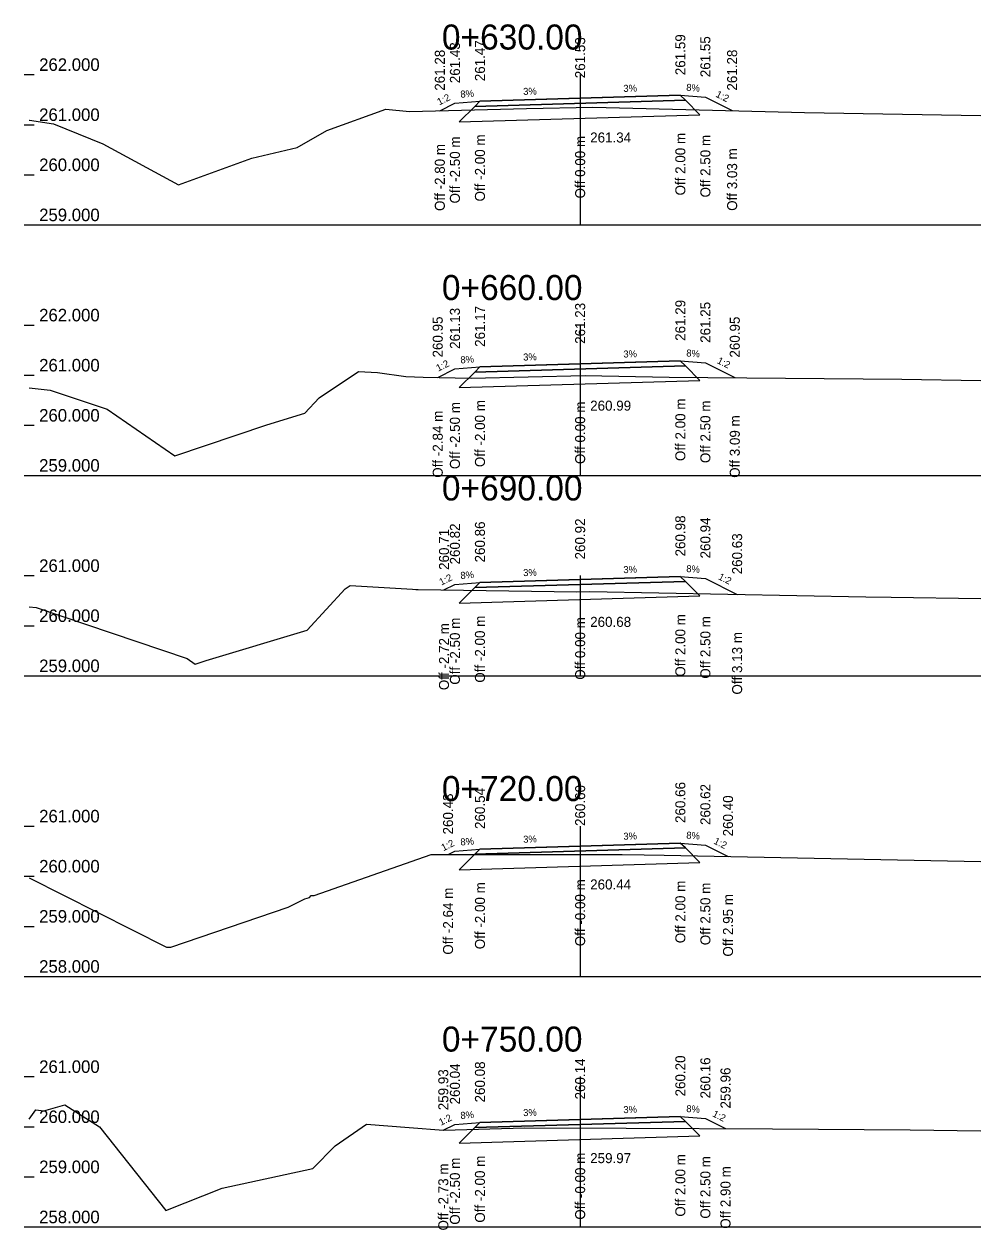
# Model space of a CAD drawing. Extents: x -550605 to -538780, y -1102367 to -1093705.
# Drawn here: x -541289.9 to -541270.8, y -1098198.61 to -1098174.55 of the extents above; entities that cross this region are included whole.
import ezdxf

# ---------------------------------------------------------------- set-up
doc = ezdxf.new("R2010")
doc.units = 0
for name, color, linetype in [('PŘ - offsety od osy', 7, 'Continuous'), ('PŘ - popis', 7, 'Continuous'), ('PŘ - příčné sklony', 7, 'Continuous'), ('PŘ - terén', 7, 'Continuous'), ('PŘ - vozovka', 7, 'Continuous'), ('PŘ - výšky offsetů', 7, 'Continuous')]:
    doc.layers.add(name, color=color, linetype=linetype)

msp = doc.modelspace()

# ---------------------------------------------------------------- linework, layer by layer
at = {"layer": 'PŘ - popis'}
for p, q in [((-541289.898, -1098175.553), (-541289.698, -1098175.553)), ((-541278.798, -1098175.553), (-541278.798, -1098178.553)), ((-541289.898, -1098176.553), (-541289.698, -1098176.553)), ((-541289.898, -1098177.553), (-541289.698, -1098177.553)), ((-541289.898, -1098178.553), (-541289.698, -1098178.553)), ((-541289.798, -1098178.553), (-541270.798, -1098178.553)), ((-541289.898, -1098180.553), (-541289.698, -1098180.553)), ((-541278.798, -1098180.553), (-541278.798, -1098183.553)), ((-541289.898, -1098181.553), (-541289.698, -1098181.553)), ((-541289.898, -1098182.553), (-541289.698, -1098182.553)), ((-541289.898, -1098183.553), (-541289.698, -1098183.553)), ((-541289.798, -1098183.553), (-541270.798, -1098183.553)), ((-541289.898, -1098185.553), (-541289.698, -1098185.553)), ((-541278.798, -1098185.553), (-541278.798, -1098187.553)), ((-541289.898, -1098186.553), (-541289.698, -1098186.553)), ((-541289.898, -1098187.553), (-541289.698, -1098187.553)), ((-541289.798, -1098187.553), (-541270.798, -1098187.553)), ((-541289.898, -1098190.553), (-541289.698, -1098190.553)), ((-541278.798, -1098190.553), (-541278.798, -1098193.553)), ((-541289.898, -1098191.553), (-541289.698, -1098191.553)), ((-541289.898, -1098192.553), (-541289.698, -1098192.553)), ((-541289.898, -1098193.553), (-541289.698, -1098193.553)), ((-541289.798, -1098193.553), (-541270.798, -1098193.553)), ((-541289.898, -1098195.553), (-541289.698, -1098195.553)), ((-541278.798, -1098195.553), (-541278.798, -1098198.553)), ((-541289.898, -1098196.553), (-541289.698, -1098196.553)), ((-541289.898, -1098197.553), (-541289.698, -1098197.553)), ((-541289.898, -1098198.553), (-541289.698, -1098198.553)), ((-541289.798, -1098198.553), (-541270.798, -1098198.553))]:
    msp.add_line(p, q, dxfattribs=at)
at = {"layer": 'PŘ - terén'}
for points in [[(-541289.798, -1098176.459), (-541289.791, -1098176.46), (-541289.312, -1098176.535), (-541288.325, -1098176.936), (-541286.816, -1098177.754), (-541286.816, -1098177.752), (-541285.351, -1098177.22), (-541284.446, -1098177.011), (-541283.853, -1098176.666), (-541282.674, -1098176.241), (-541282.207, -1098176.291), (-541279.867, -1098176.228), (-541278.543, -1098176.203), (-541278.542, -1098176.203), (-541276.153, -1098176.261), (-541274.321, -1098176.311), (-541270.798, -1098176.367)], [(-541289.798, -1098181.803), (-541289.377, -1098181.848), (-541288.241, -1098182.233), (-541286.888, -1098183.16), (-541286.888, -1098183.16), (-541286.887, -1098183.161), (-541285.055, -1098182.541), (-541284.294, -1098182.313), (-541284.007, -1098182.002), (-541283.22, -1098181.48), (-541282.846, -1098181.5), (-541282.279, -1098181.576), (-541281.93, -1098181.595), (-541280.976, -1098181.609), (-541278.697, -1098181.558), (-541278.697, -1098181.558), (-541277.022, -1098181.589), (-541272.374, -1098181.631), (-541270.798, -1098181.657)], [(-541289.798, -1098186.173), (-541289.658, -1098186.188), (-541286.645, -1098187.208), (-541286.485, -1098187.318), (-541286.485, -1098187.318), (-541286.481, -1098187.321), (-541286.265, -1098187.248), (-541284.249, -1098186.643), (-541283.489, -1098185.819), (-541283.389, -1098185.753), (-541282.144, -1098185.82), (-541282.075, -1098185.829), (-541282.032, -1098185.831), (-541278.865, -1098185.878), (-541278.603, -1098185.872), (-541278.603, -1098185.872), (-541273.094, -1098185.975), (-541272.587, -1098185.98), (-541270.798, -1098186.01)], [(-541289.798, -1098191.588), (-541287.058, -1098192.969), (-541286.971, -1098192.967), (-541284.629, -1098192.169), (-541284.294, -1098192.001), (-541284.203, -1098191.974), (-541284.168, -1098191.936), (-541284.111, -1098191.939), (-541281.771, -1098191.116), (-541281.771, -1098191.116), (-541281.557, -1098191.119), (-541277.959, -1098191.116), (-541277.521, -1098191.125), (-541277.122, -1098191.131), (-541270.798, -1098191.257)], [(-541289.798, -1098196.402), (-541289.661, -1098196.216), (-541289.506, -1098196.236), (-541289.087, -1098196.114), (-541288.396, -1098196.553), (-541287.07, -1098198.225), (-541287.068, -1098198.226), (-541285.942, -1098197.778), (-541284.135, -1098197.383), (-541283.688, -1098196.933), (-541283.064, -1098196.503), (-541282.213, -1098196.566), (-541281.529, -1098196.624), (-541281.528, -1098196.623), (-541279.899, -1098196.576), (-541277.881, -1098196.581), (-541274.956, -1098196.593), (-541272.213, -1098196.616), (-541270.798, -1098196.637)]]:
    msp.add_lwpolyline(points, dxfattribs=at)
at = {"layer": 'PŘ - vozovka'}
for points in [[(-541281.599, -1098176.275), (-541281.298, -1098176.125), (-541280.798, -1098176.085), (-541278.798, -1098176.025), (-541276.798, -1098175.965), (-541276.298, -1098176.005), (-541275.764, -1098176.272)], [(-541281.641, -1098181.599), (-541281.298, -1098181.427), (-541280.798, -1098181.387), (-541278.798, -1098181.327), (-541276.798, -1098181.267), (-541276.298, -1098181.307), (-541275.711, -1098181.601)], [(-541281.516, -1098185.839), (-541281.298, -1098185.73), (-541280.798, -1098185.69), (-541278.798, -1098185.63), (-541276.798, -1098185.57), (-541276.298, -1098185.61), (-541275.664, -1098185.927)], [(-541281.435, -1098191.119), (-541281.298, -1098191.05), (-541280.798, -1098191.01), (-541278.798, -1098190.95), (-541276.798, -1098190.89), (-541276.298, -1098190.93), (-541275.846, -1098191.157)], [(-541281.53, -1098196.624), (-541281.298, -1098196.508), (-541280.798, -1098196.468), (-541278.798, -1098196.408), (-541276.798, -1098196.348), (-541276.298, -1098196.388), (-541275.896, -1098196.589)]]:
    msp.add_lwpolyline(points, dxfattribs=at)
for points in [[(-541280.898, -1098176.188), (-541281.211, -1098176.497), (-541276.409, -1098176.353), (-541276.698, -1098176.062)], [(-541280.798, -1098176.085), (-541280.898, -1098176.188), (-541276.698, -1098176.062), (-541276.798, -1098175.965)], [(-541280.898, -1098181.49), (-541281.211, -1098181.8), (-541276.409, -1098181.656), (-541276.698, -1098181.364)], [(-541280.798, -1098181.387), (-541280.898, -1098181.49), (-541276.698, -1098181.364), (-541276.798, -1098181.267)], [(-541280.898, -1098185.793), (-541281.211, -1098186.102), (-541276.409, -1098185.958), (-541276.698, -1098185.667)], [(-541280.798, -1098185.69), (-541280.898, -1098185.793), (-541276.698, -1098185.667), (-541276.798, -1098185.57)], [(-541280.898, -1098191.113), (-541281.211, -1098191.423), (-541276.409, -1098191.279), (-541276.698, -1098190.987)], [(-541280.798, -1098191.01), (-541280.898, -1098191.113), (-541276.698, -1098190.987), (-541276.798, -1098190.89)], [(-541280.798, -1098196.468), (-541280.898, -1098196.571), (-541276.698, -1098196.445), (-541276.798, -1098196.348)], [(-541280.898, -1098196.571), (-541281.211, -1098196.881), (-541276.409, -1098196.737), (-541276.698, -1098196.445)]]:
    msp.add_lwpolyline(points, close=True, dxfattribs=at)

# ---------------------------------------------------------------- texts
at = {"layer": 'PŘ - offsety od osy'}
for s, p in [('Off -2.50 m', (-541281.198, -1098178.125)), ('Off -2.00 m', (-541280.698, -1098178.085)), ('Off 0.00 m', (-541278.698, -1098178.025)), ('Off 2.00 m', (-541276.698, -1098177.965)), ('Off 2.50 m', (-541276.198, -1098178.005)), ('Off -2.80 m', (-541281.499, -1098178.275)), ('Off 3.03 m', (-541275.664, -1098178.272)), ('Off -2.50 m', (-541281.198, -1098183.427)), ('Off -2.00 m', (-541280.698, -1098183.387)), ('Off 0.00 m', (-541278.698, -1098183.327)), ('Off 2.00 m', (-541276.698, -1098183.267)), ('Off 2.50 m', (-541276.198, -1098183.307)), ('Off -2.84 m', (-541281.541, -1098183.599)), ('Off 3.09 m', (-541275.611, -1098183.601)), ('Off -2.50 m', (-541281.198, -1098187.73)), ('Off -2.00 m', (-541280.698, -1098187.69)), ('Off 0.00 m', (-541278.698, -1098187.63)), ('Off 2.00 m', (-541276.698, -1098187.57)), ('Off 2.50 m', (-541276.198, -1098187.61)), ('Off -2.72 m', (-541281.416, -1098187.839)), ('Off 3.13 m', (-541275.564, -1098187.927)), ('Off -2.00 m', (-541280.698, -1098193.01)), ('Off -0.00 m', (-541278.698, -1098192.95)), ('Off 2.00 m', (-541276.698, -1098192.89)), ('Off 2.50 m', (-541276.198, -1098192.93)), ('Off -2.64 m', (-541281.335, -1098193.119)), ('Off 2.95 m', (-541275.746, -1098193.157)), ('Off -2.73 m', (-541281.43, -1098198.624)), ('Off -2.50 m', (-541281.198, -1098198.508)), ('Off -2.00 m', (-541280.698, -1098198.468)), ('Off -0.00 m', (-541278.698, -1098198.408)), ('Off 2.00 m', (-541276.698, -1098198.348)), ('Off 2.50 m', (-541276.198, -1098198.388)), ('Off 2.90 m', (-541275.796, -1098198.589))]:
    msp.add_text(s, height=0.2, rotation=90, dxfattribs=at).set_placement(p)
at = {"layer": 'PŘ - popis'}
for s, height, p in [('0+630.00', 0.5, (-541281.558, -1098175.053)), ('262.000', 0.25, (-541289.598, -1098175.478)), ('261.000', 0.25, (-541289.598, -1098176.478)), ('260.000', 0.25, (-541289.598, -1098177.478)), ('259.000', 0.25, (-541289.598, -1098178.478)), ('0+660.00', 0.5, (-541281.558, -1098180.053)), ('262.000', 0.25, (-541289.598, -1098180.478)), ('261.000', 0.25, (-541289.598, -1098181.478)), ('260.000', 0.25, (-541289.598, -1098182.478)), ('259.000', 0.25, (-541289.598, -1098183.478)), ('0+690.00', 0.5, (-541281.558, -1098184.053)), ('261.000', 0.25, (-541289.598, -1098185.478)), ('260.000', 0.25, (-541289.598, -1098186.478)), ('259.000', 0.25, (-541289.598, -1098187.478)), ('0+720.00', 0.5, (-541281.558, -1098190.053)), ('261.000', 0.25, (-541289.598, -1098190.478)), ('260.000', 0.25, (-541289.598, -1098191.478)), ('259.000', 0.25, (-541289.598, -1098192.478)), ('258.000', 0.25, (-541289.598, -1098193.478)), ('0+750.00', 0.5, (-541281.558, -1098195.053)), ('261.000', 0.25, (-541289.598, -1098195.478)), ('260.000', 0.25, (-541289.598, -1098196.478)), ('259.000', 0.25, (-541289.598, -1098197.478)), ('258.000', 0.25, (-541289.598, -1098198.478))]:
    msp.add_text(s, height=height, dxfattribs=at).set_placement(p)
at = {"layer": 'PŘ - příčné sklony'}
for s, rotation, p in [('8%', 4.5739, (-541281.183, -1098176.015)), ('3%', 1.7184, (-541279.933, -1098175.959)), ('3%', 1.7184, (-541277.933, -1098175.899)), ('8%', 355.4261, (-541276.683, -1098175.874)), ('1:2', 333.4349, (-541276.103, -1098175.99)), ('1:2', 26.5651, (-541281.61, -1098176.169)), ('8%', 4.5739, (-541281.183, -1098181.318)), ('3%', 1.7184, (-541279.933, -1098181.261)), ('3%', 1.7184, (-541277.933, -1098181.201)), ('8%', 355.4261, (-541276.683, -1098181.176)), ('1:2', 26.5651, (-541281.631, -1098181.482)), ('1:2', 333.4349, (-541276.077, -1098181.306)), ('1:2', 26.5651, (-541281.569, -1098185.753)), ('8%', 4.5739, (-541281.183, -1098185.621)), ('3%', 1.7184, (-541279.933, -1098185.564)), ('3%', 1.7184, (-541277.933, -1098185.504)), ('8%', 355.4261, (-541276.683, -1098185.479)), ('1:2', 333.4349, (-541276.053, -1098185.62)), ('1:2', 26.5651, (-541281.528, -1098191.054)), ('8%', 4.5739, (-541281.183, -1098190.941)), ('3%', 1.7184, (-541279.933, -1098190.885)), ('3%', 1.7184, (-541277.933, -1098190.825)), ('8%', 355.4261, (-541276.683, -1098190.8)), ('1:2', 333.4349, (-541276.144, -1098190.896)), ('8%', 355.4261, (-541276.683, -1098196.257)), ('1:2', 26.5651, (-541281.576, -1098196.535)), ('8%', 4.5739, (-541281.183, -1098196.399)), ('3%', 1.7184, (-541279.933, -1098196.342)), ('3%', 1.7184, (-541277.933, -1098196.282)), ('1:2', 333.4349, (-541276.169, -1098196.341))]:
    msp.add_text(s, height=0.14, rotation=rotation, dxfattribs=at).set_placement(p)
at = {"layer": 'PŘ - výšky offsetů'}
for s, p in [('261.43', (-541281.198, -1098175.725)), ('261.47', (-541280.698, -1098175.685)), ('261.53', (-541278.698, -1098175.625)), ('261.59', (-541276.698, -1098175.565)), ('261.55', (-541276.198, -1098175.605)), ('261.28', (-541281.499, -1098175.875)), ('261.28', (-541275.664, -1098175.872)), ('261.13', (-541281.198, -1098181.027)), ('261.17', (-541280.698, -1098180.987)), ('261.23', (-541278.698, -1098180.927)), ('261.29', (-541276.698, -1098180.867)), ('261.25', (-541276.198, -1098180.907)), ('260.95', (-541281.541, -1098181.199)), ('260.95', (-541275.611, -1098181.201)), ('260.82', (-541281.198, -1098185.33)), ('260.86', (-541280.698, -1098185.29)), ('260.92', (-541278.698, -1098185.23)), ('260.98', (-541276.698, -1098185.17)), ('260.94', (-541276.198, -1098185.21)), ('260.71', (-541281.416, -1098185.439)), ('260.63', (-541275.564, -1098185.527)), ('260.54', (-541280.698, -1098190.61)), ('260.60', (-541278.698, -1098190.55)), ('260.66', (-541276.698, -1098190.49)), ('260.62', (-541276.198, -1098190.53)), ('260.43', (-541281.335, -1098190.719)), ('260.40', (-541275.746, -1098190.757)), ('260.20', (-541276.698, -1098195.948)), ('260.04', (-541281.198, -1098196.108)), ('260.08', (-541280.698, -1098196.068)), ('260.14', (-541278.698, -1098196.008)), ('260.16', (-541276.198, -1098195.988)), ('259.96', (-541275.796, -1098196.189)), ('259.93', (-541281.43, -1098196.224))]:
    msp.add_text(s, height=0.2, rotation=90, dxfattribs=at).set_placement(p)
for s, p in [('261.34', (-541278.598, -1098176.908)), ('260.99', (-541278.598, -1098182.26)), ('260.68', (-541278.598, -1098186.576)), ('260.44', (-541278.598, -1098191.817)), ('259.97', (-541278.598, -1098197.279))]:
    msp.add_text(s, height=0.2, dxfattribs=at).set_placement(p)

doc.saveas('drawing.dxf')
